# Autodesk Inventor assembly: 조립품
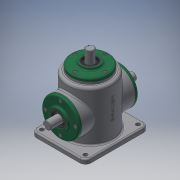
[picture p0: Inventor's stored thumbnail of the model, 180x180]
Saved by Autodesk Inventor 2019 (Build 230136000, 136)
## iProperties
Created: 2020-12
Part Number: 조립품
Material: 일반
Document SubType Name: Assembly
Designer: jun-1-3
Author: jun-1-3
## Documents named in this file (16)
- C:\Users\jun-1-3\Desktop\701207V1001\조립품.iam
- C:\Users\jun-1-3\Desktop\701207V1001\본체.ipt
- C:\Users\jun-1-3\Desktop\701207V1001\메인 베벨기어.ipt
- C:\Users\jun-1-3\Desktop\701207V1001\메인 축.ipt
- 메인 축.ipt
- C:\Users\jun-1-3\Desktop\701207V1001\베어링 6203.ipt
- C:\Users\jun-1-3\Desktop\701207V1001\볼트 M4.ipt
- 볼트 M4.ipt
- C:\Users\jun-1-3\Desktop\701207V1001\서브 베벨기어.ipt
- C:\Users\jun-1-3\Desktop\701207V1001\서브 축.ipt
- 서브 축.ipt
- C:\Users\jun-1-3\Desktop\701207V1001\오일 실.ipt
- 오일 실.ipt
- C:\Users\jun-1-3\Desktop\701207V1001\커버.ipt
- C:\Users\jun-1-3\Desktop\701207V1001\키 4x4.ipt
- C:\Users\jun-1-3\Desktop\701207V1001\키 5x5.ipt
